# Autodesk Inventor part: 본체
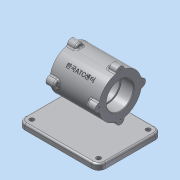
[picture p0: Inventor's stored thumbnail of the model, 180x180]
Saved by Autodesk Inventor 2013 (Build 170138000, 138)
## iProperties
Created: 2015-12
Part Number: 본체
Material: 알루미늄 6061
Document SubType Name: Modeling
Designer: dgall
Density: 2.71 g/cm^3
Mass: 1166.59 g
Surface Area: 817.857 cm^2
Volume: 430.475 cm^3
Author: dgall
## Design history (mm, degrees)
sketch "스케치1"
  geometry: L1 (0, 0)-(85, 0); L2 (0, 23.5)-(22, 23.5); L3 (22, 23.5)-(22, 21); L4 (22, 21)-(63, 21); L5 (63, 21)-(63, 23.5); L6 (63, 23.5)-(85, 23.5); L7 (85, 23.5)-(85, 37); L8 (85, 37)-(0, 37); L9 (0, 37)-(0, 23.5)
  constraints: 18 end point, 5 parallel, 3 perpendicular, 1 horizontal
  dimensions: "d0" = 85 distance of L1.start L1.end; "d1" = 74 diameter of L8 L1; "d3" = 85 distance between parallel lines of L7 L9; "d4" = 0 distance from line of L1.start L9; "d5" = 47 diameter of L2 L1; "d6" = 42 diameter of L4 L1; "d7" = 47 diameter of L6 L1; "d8" = 22 distance of L2.start L2.end; "d9" = 41 distance of L3.end L4.end
revolve "회전1" sketch "스케치1" stored, may be unused: angle "d10" = 90 deg
sketch "스케치2"
  geometry: L1 (-37, 0)-(37, 0); L2 (0, 37)-(0, -37); A1 r 7 centre (-37, 0) between (-36.338, 6.969) and (-36.338, -6.969); A2 r 7 centre (0, 37) between (6.969, 36.338) and (-6.969, 36.338); A3 r 7 centre (37, 0) between (36.338, -6.969) and (36.338, 6.969); A4 r 7 centre (0, -37) between (-6.969, -36.338) and (6.969, -36.338); 1 further point
  constraints: 8 point on circle, 4 centre point, 4 end point, 1 horizontal, 1 perpendicular, 13 other
  dimensions: "d11" = 14 diameter of A4; "d13" = 14 diameter of A1; "d14" = 14 diameter of A2; "d15" = 14 diameter of A3
extrude "돌출1" join sketch "스케치2" distance "d16" = 15; taper "d17" = 0 deg
node "작업 평면1"
fillet "모깎기1" dims "d19" = 0.3
chamfer "모따기1" distance "d20" = 1; stored, may be unused: second distance "d21" = 2, angle "d22" = 45 deg
chamfer "모따기2" distance "d23" = 1; stored, may be unused: second distance "d24" = 2, angle "d25" = 45 deg
sketch "스케치3"
  geometry: A1 r 7 centre (0, 0) between (0.662, 6.969) and (0.662, -6.969) reference; A2 r 7 centre (37, -37) between (30.031, -36.338) and (43.969, -36.338) reference; A3 r 7 centre (74, 0) between (73.338, -6.969) and (73.338, 6.969) reference; A4 r 7 centre (37, 37) between (43.969, 36.338) and (30.031, 36.338) reference
sketch "스케치4"
  geometry: A1 r 7 centre (37, 37) between (43.969, 36.338) and (30.031, 36.338) reference; A2 r 7 centre (0, 0) between (0.662, 6.969) and (0.662, -6.969) reference; A3 r 7 centre (37, -37) between (30.031, -36.338) and (43.969, -36.338) reference; A4 r 7 centre (74, 0) between (73.338, -6.969) and (73.338, 6.969) reference
hole "구멍1" sketch "스케치4" at (74, 0), (37, -37), (0, 0), (37, 37) diameter "d26" = 3.242; stored, may be unused: countersink angle "d30" = 90 deg, drill point angle "d32" = 118 deg; dims "d27" = 9, "d28" = 4, "d29" = 2, "d31" = 11
hole "구멍2" sketch "스케치3" diameter "d33" = 3.242; stored, may be unused: countersink angle "d37" = 90 deg, drill point angle "d39" = 118 deg; dims "d34" = 9, "d35" = 4, "d36" = 2, "d38" = 11
node "작업 평면2"
sketch "스케치5"
  geometry: L1 (15, 37)-(70, 37) reference; L2 (70, 44)-(70, 36.338) reference; L3 (85, 44)-(70, 44) reference; L4 (85, 36.338)-(85, 44) reference; L5 (85, 6.969)-(85, 36.338) reference; L6 (85, -7)-(85, 7) reference; L7 (85, -36.338)-(85, -6.969) reference; L8 (85, -44)-(85, -36.338) reference; L9 (85, -44)-(70, -44) reference; L10 (70, -36.338)-(70, -44) reference; L11 (15, -37)-(70, -37) reference; L12 (15, -36.338)-(15, -44) reference; L13 (15, -44)-(0, -44) reference; L14 (0, -44)-(0, -36.338) reference; L15 (0, -36.338)-(0, -6.969) reference; L16 (0, 6.969)-(0, 36.338) reference; L17 (0, -7)-(0, 7) reference; L18 (0, 36.338)-(0, 44) reference; L19 (15, 44)-(0, 44) reference; L20 (15, 44)-(15, 36.338) reference; L21 (-37.5, 55)-(102.5, 55); L22 (102.5, 55)-(102.5, -55); L23 (102.5, -55)-(-37.5, -55); L24 (-37.5, -55)-(-37.5, 55); L25 (0, 0)-(85, 0); L26 (42.5, -37)-(42.5, 37)
  constraints: 12 end point, 3 midpoint, 2 parallel, 1 horizontal, 1 perpendicular
  dimensions: "d41" = 140 distance of L21.start L21.end; "d43" = 110 distance of L21.end L22.end; "d44" = 55 distance between parallel lines of L25 L21; "d45" = 80 distance between parallel lines of L26 L24
node "작업 평면4"
  node "작업 평면3"
sketch "스케치9"
  geometry: L1 (15, -30.622)-(15, -20.767) reference; L2 (15, -20.767)-(0, -20.767) reference; L3 (0, -20.767)-(0, 20.767) reference; L4 (0, 20.767)-(15, 20.767) reference; L5 (15, 20.767)-(15, 30.622) reference; L6 (15, 30.622)-(0, 30.622) reference; L7 (0, 30.622)-(0, 30.622) reference; L8 (0, 30.622)-(15, 30.622) reference; L9 (15, 30.622)-(15, 20.767) reference; L10 (15, 20.767)-(0, 20.767) reference; L11 (0, 20.767)-(0, -20.767) reference; L12 (0, -20.767)-(15, -20.767) reference; L13 (15, -20.767)-(15, -30.622) reference; L14 (15, -30.622)-(0, -30.622) reference; L15 (0, -30.622)-(0, -30.622) reference; L16 (0, -30.622)-(15, -30.622) reference; L17 (70, -20.767)-(70, -30.622) reference; L18 (70, -30.622)-(85, -30.622) reference; L19 (85, -30.622)-(85, -30.622) reference; L20 (85, -30.622)-(70, -30.622) reference; L21 (70, -30.622)-(70, -20.767) reference; L22 (70, -20.767)-(85, -20.767) reference; L23 (85, 20.767)-(85, -20.767) reference; L24 (85, 20.767)-(70, 20.767) reference; L25 (70, 20.767)-(70, 30.622) reference; L26 (70, 30.622)-(85, 30.622) reference; L27 (85, 30.622)-(85, 30.622) reference; L28 (85, 30.622)-(70, 30.622) reference; L29 (70, 30.622)-(70, 20.767) reference; L30 (70, 20.767)-(85, 20.767) reference; L31 (85, -20.767)-(85, 20.767) reference; L32 (85, -20.767)-(70, -20.767) reference; L33 (0, 37)-(85, 37) reference; L34 (42.5, 37)-(42.5, -2.606); L35 (17.613, 3.602)-(67.387, 3.602); L36 (67.387, 3.602)-(67.387, -3.602); L37 (67.387, -3.602)-(17.613, -3.602); L38 (17.613, -3.602)-(17.613, 3.602); L39 (17.613, 0)-(67.387, 0); L40 (42.5, 3.602)-(42.5, -3.602); 1 further point
  constraints: 6 end point, 5 midpoint, 1 perpendicular, 2 other
  dimensions: "d94" = 0 distance between parallel lines of L34 L40; "d96" = 0 distance from line of point (0, 0) L39
feature "엠보싱1" sketch "스케치9" dims "d0" = 85, "d1" = 74, "d3" = 85, "d4" = 0, "d5" = 47, "d6" = 42, "d7" = 47, "d8" = 22, "d9" = 41, "d11" = 14, "d13" = 14, "d14" = 14, "d15" = 14, "d97" = 0.5, "d98" = 0
fillet "모깎기7" dims "d100" = 3
fillet "모깎기8" dims "d101" = 3
extrude "돌출5" join sketch "스케치5" distance "d103" = 10; taper "d104" = 0 deg
fillet "모깎기9" dims "d105" = 12
fillet "모깎기10" dims "d106" = 3
sketch "스케치12"
  geometry: C1 r 4 at (-25.5, 43); C2 r 4 at (-25.5, -43); C3 r 4 at (90.5, -43); C4 r 4 at (90.5, 43); A1 r 9 centre (90.5, -43) between (90.5, -52) and (99.5, -43) reference; A2 r 9 centre (90.5, 43) between (99.5, 43) and (90.5, 52) reference; A3 r 9 centre (-25.5, 43) between (-25.5, 52) and (-34.5, 43) reference; A4 r 9 centre (-25.5, -43) between (-34.5, -43) and (-25.5, -52) reference; 1 further point
  constraints: 4 centre point, 4 coincident
  dimensions: "d107" = 8 diameter of C1; "d109" = 8 diameter of C4; "d110" = 8 diameter of C3; "d111" = 8 diameter of C2
extrude "돌출6" cut sketch "스케치12" distance "d112" = 10; taper "d113" = 0 deg
node "솔리드1"
mirror "대칭1"
node "투영된 루프3"
other parameters: "d18" = 42.5, "d57" = 37, "d58" = 37, "d92" = 45 deg, "d93" = 81.5
